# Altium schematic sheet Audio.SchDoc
size A4; DocumentNumber: 4; Revision: C.1(PCB.SCH); SheetNumber: 4; SheetTotal: 6
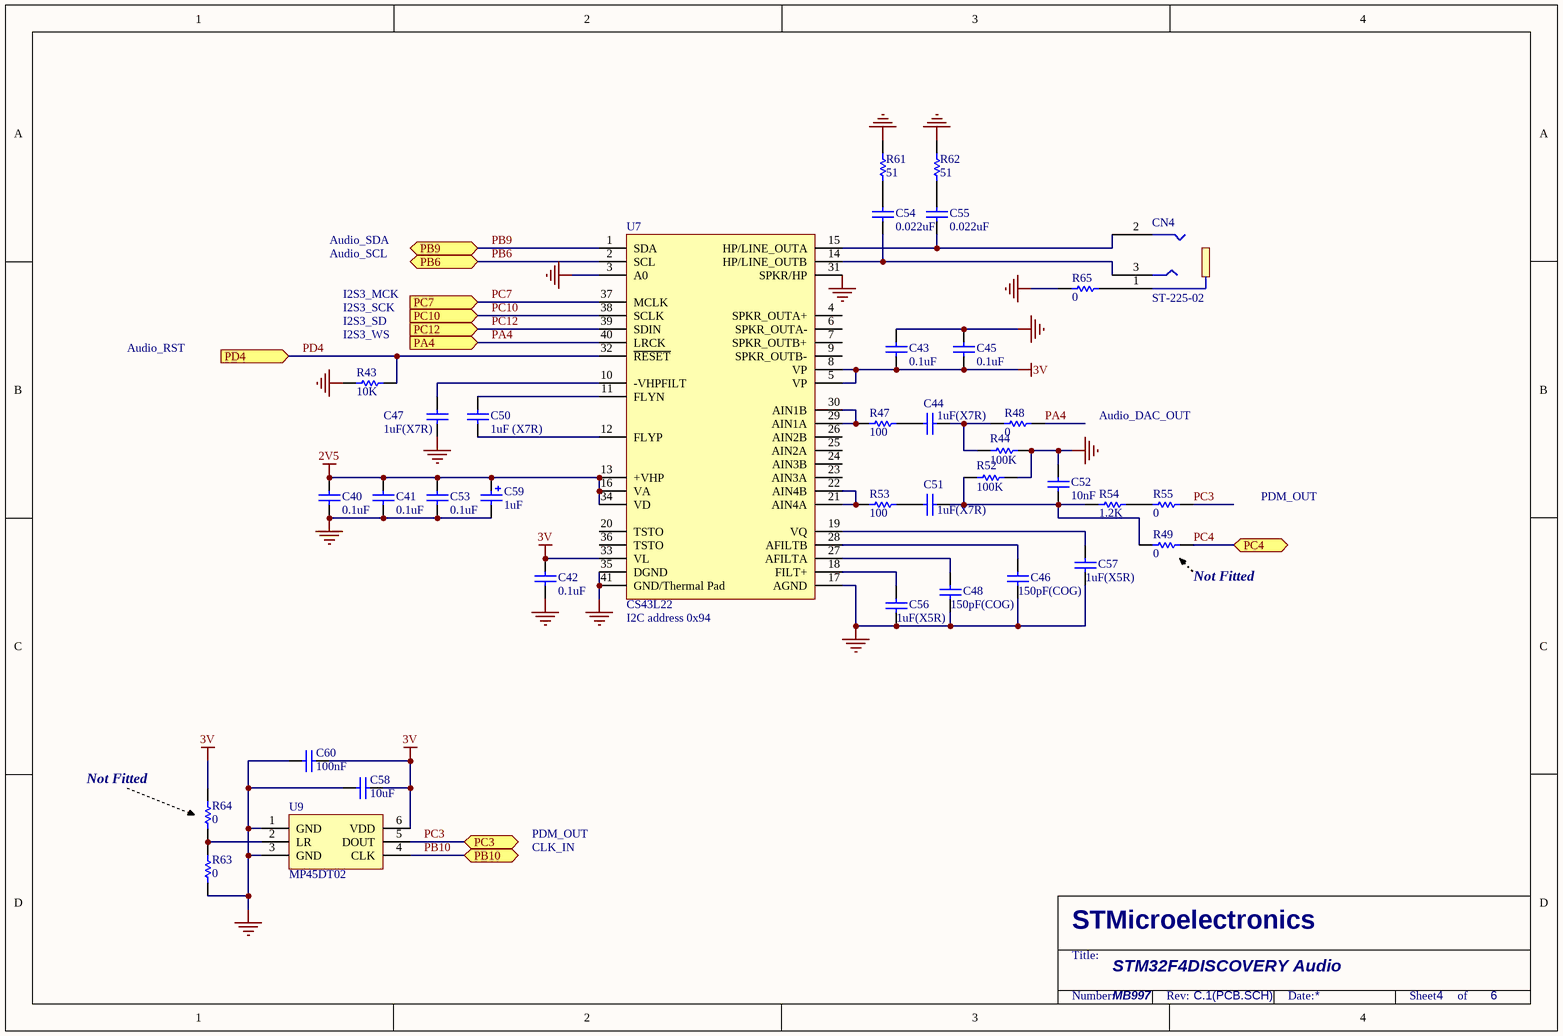
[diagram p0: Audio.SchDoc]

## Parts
C40  0.1uF  [0402C]
C41  0.1uF  [0402C]
C42  0.1uF  [0402C]
C43  0.1uF  [0402C]
C44  1uF(X7R)  [0603C]
C45  0.1uF  [0402C]
C46  150pF(COG)  [0603C]
C47  1uF(X7R)  [0603C]
C48  150pF(COG)  [0603C]
C50  1uF (X7R)  [0603C]
C51  1uF(X7R)  [0603C]
C52  10nF  [0603C]
C53  0.1uF  [0402C]
C54  0.022uF  [0603C]
C55  0.022uF  [0603C]
C56  1uF(X5R)  [0603C]
C57  1uF(X5R)  [0603C]
C58  10uF  [0603C]
C59  1uF  [TAN-A]
C60  100nF  [0603C]
CN4  ST-225-02  [Jack-ST-225]
R43  10K  [0402R]
R44  100K  [0402R]
R47  100  [0603R]
R48  0  [0402R]
R49  0  [0402R]
R52  100K  [0402R]
R53  100  [0603R]
R54  1.2K  [0603R]
R55  0  [0402R]
R61  51  [0603R]
R62  51  [0603R]
R63  0  [0402R]
R64  0  [0402R]
R65  0  [0402R]
U7  CS43L22  [QFN40]
U9  MP45DT02  [HLGA-4.72-3.76-6LD]

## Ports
PA4 (in), PB6 (bidir), PB9 (bidir), PB10, PC3, PC4, PC7 (in), PC10 (in), PC12 (in), PD4 (in)

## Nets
2V5: C40.2 C41.2 C53.2 C59.1 U7.13(+VHP) U7.16(VA) U7.34(VD)
3V: C42.2 C43.2 C45.2 C58.2 C60.2 R64.2 U7.5(VP) U7.8(VP) U7.33(VL) U9.6(VDD)
GND: C40.1 C41.1 C42.1 C43.1 C45.1 C46.1 C47.2 C48.1 C52.2 C53.1 C56.1 C57.1 C58.1 C59.2 C60.1 R43.2 R44.2 R52.2 R61.1 R62.1 R63.1 R65.2 U7.3(A0) U7.17(AGND) U7.31(SPKR/HP) U7.35(DGND) U7.41(GND/Thermal_Pad) U9.1(GND) U9.3(GND)
PA4: R48.1 U7.40(LRCK) ; port PA4
PB6: U7.2(SCL) ; port PB6
PB9: U7.1(SDA) ; port PB9
PB10: U9.4(CLK) ; port PB10
PC3: R55.1 U9.5(DOUT) ; port PC3
PC4: R49.1 ; port PC4
PC7: U7.37(MCLK) ; port PC7
PC10: U7.38(SCLK) ; port PC10
PC12: U7.39(SDIN) ; port PC12
PD4: R43.1 U7.32(~{RESET}) ; port PD4
NetC44_1: C44.1 R47.1
NetC44_2: C44.2 R44.1 R48.2
NetC46_2: C46.2 U7.28(AFILTB)
NetC47_1: C47.1 U7.10(-VHPFILT)
NetC48_2: C48.2 U7.27(AFILTA)
NetC50_1: C50.1 U7.12(FLYP)
NetC50_2: C50.2 U7.11(FLYN)
NetC51_1: C51.1 R53.1
NetC51_2: C51.2 C52.1 R49.2 R52.1 R54.1
NetC54_1: C54.1 R61.2
NetC54_2: C54.2 CN4.3 U7.14(HP/LINE_OUTB)
NetC55_1: C55.1 R62.2
NetC55_2: C55.2 CN4.2 U7.15(HP/LINE_OUTA)
NetC56_2: C56.2 U7.18(FILT+)
NetC57_2: C57.2 U7.19(VQ)
NetCN4_1: CN4.1 R65.1
NetR47_2: R47.2 U7.29(AIN1A) U7.30(AIN1B)
NetR53_2: R53.2 U7.21(AIN4A) U7.22(AIN4B)
NetR54_2: R54.2 R55.2
NetR63_2: R63.2 R64.1 U9.2(LR)

Not connected (* = marked no-connect by the designer): U7 4(SPKR_OUTA+) 6(SPKR_OUTA-) 7(SPKR_OUTB+) 9(SPKR_OUTB-) 20(TSTO) 23(AIN3A) 24(AIN3B) 25(AIN2A) 26(AIN2B) 36(TSTO)

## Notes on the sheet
- Audio_SDA
- Audio_SCL
- I2S3_MCK
- I2S3_SCK
- Audio_RST
- (near R43) I2S3_WS
- I2S3_SD
- Audio_DAC_OUT
- PDM_OUT
- (near R49) Not Fitted
- (near U7) I2C address 0x94
- (near R64) Not Fitted
- CLK_IN
- STM32F4DISCOVERY Audio
- MB997

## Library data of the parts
C40-C48 C50-C58 = CAP: Capacitor; Value: 100nF
C59 = Cap Pol1: Polarized Capacitor (Radial); Value: 47uF
C60 = CAP: Capacitor
CN4 = ST-225-02: Connector Jack 35mm; Manuf_1: XIEJIA Electronics
R43 R44 R47 R48 R52 R53 R55 R61 R62 R65 = res1: Resistor; Value: 1K
R49 = res1: Resistor; Value: 1K; Fitted: NO
R54 R63 = res1: Resistor
R64 = res1: Resistor; Fitted: NO
U7 = CS43L22: Low Power, Stereo DAC w/Headphone & Speaker Amps
U9 = MP45DT02: MEMS audio sensor, omnidirectional digital microphone; Manuf_1: STM; Provided: ST; Ref St: 9188006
